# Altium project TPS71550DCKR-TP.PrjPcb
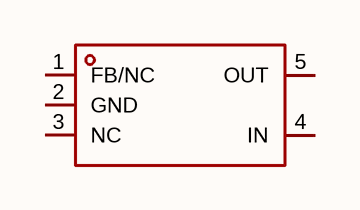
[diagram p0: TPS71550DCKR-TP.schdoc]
1 sheet, 1 parts. Net scope: global (net labels, ports and power ports of the same name join across sheets).

## Sheet TPS71550DCKR-TP.schdoc
size 127 x 101 mm

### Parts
U?  tps71550dckr-tp  [SC-70-5_L2.1-W1.3-P0.65-LS2.1-BR]  (value not drawn)

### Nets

Not connected (* = marked no-connect by the designer): U? 1(FB/NC) 2(GND) 3(NC) 4(IN) 5(OUT)

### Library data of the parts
U? = tps71550dckr-tp: 输出极性:正极;工作电压:24V;输出电压:5V;输出电流:50mA;电源纹波抑制比(PSRR):60dB@(100kHz);输出类型:固定;; Manufacturer: TECH PUBLIC(台舟); AddInBom: yes; ModelId: e25de95d33824a3dab7086d8b5286abf; ModelName: SC-70-5_L2.1-W1.3-H1.0-LS2.1-P0.65; ModelTransform: 82.677,78.74,0,180,0,0,0,0,0; Output Configuration: 正极; Voltage - Supply: 24V; Output Voltage: 5V; Output Current: 50mA; Output Type: 固定; Number of Outputs: 1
